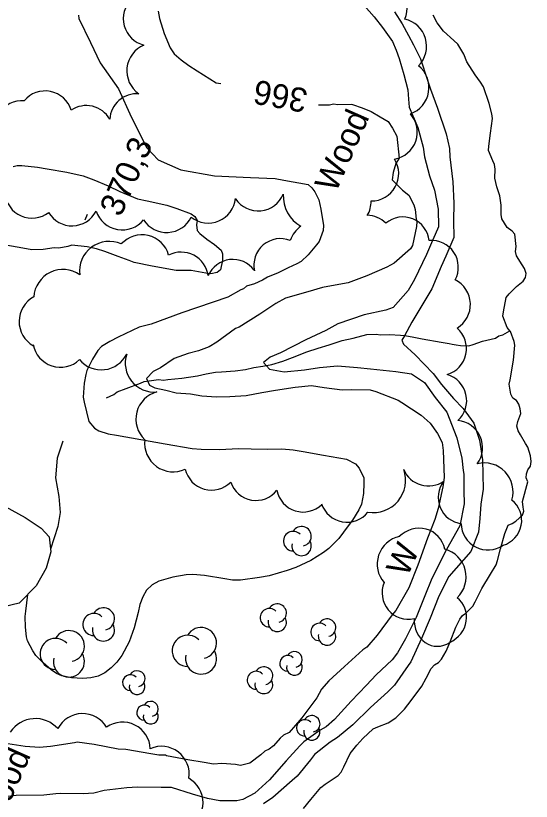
# Model space of a CAD drawing. Extents: x 287698 to 290158, y 5234163 to 5237182.
# Drawn here: x 289223.4 to 289287.7, y 5234946.9 to 5235044.9 of the extents above; entities that cross this region are included whole.
import ezdxf

# ---------------------------------------------------------------- set-up
doc = ezdxf.new("R2010")
doc.units = 0
for name, color, linetype in [('Niveau 1', 7, 'Continuous'), ('Niveau 19', 7, 'Continuous'), ('Niveau 2', 7, 'Continuous'), ('Niveau 21', 7, 'Continuous'), ('Niveau 3', 7, 'Continuous'), ('Niveau 4', 7, 'Continuous'), ('Niveau 44', 7, 'Continuous')]:
    doc.layers.add(name, color=color, linetype=linetype)

msp = doc.modelspace()

# ---------------------------------------------------------------- linework, layer by layer
at = {"layer": 'Niveau 1'}
for points in [[(289223.06, 5235026.08), (289223.56, 5235026.2), (289224.13, 5235026.2), (289226.09, 5235026.02), (289227.29, 5235025.81), (289229.76, 5235025.37), (289231.77, 5235024.91), (289233.12, 5235024.41), (289234.92, 5235023.67), (289236.38, 5235022.96), (289238.57, 5235022.03), (289239.79, 5235021.79), (289242.23, 5235021.24), (289243.46, 5235020.84), (289245.25, 5235020.18), (289245.74, 5235019.83), (289246, 5235019.36), (289245.92, 5235018.8), (289246, 5235018.1), (289246.34, 5235017.73), (289247.21, 5235017.01), (289248.19, 5235016.35), (289249, 5235015.64), (289249.2, 5235015.18), (289249.17, 5235014.41), (289248.93, 5235013.18), (289248.52, 5235012.84), (289247.72, 5235012.68), (289247.11, 5235012.77), (289245.26, 5235013.09), (289243.41, 5235013.11)], [(289243.41, 5235013.11), (289240.42, 5235013.64), (289238.15, 5235014.1), (289237.54, 5235014.37), (289236.14, 5235014.84), (289234.49, 5235015.5), (289233.45, 5235015.82), (289232.28, 5235016.05), (289230.38, 5235016.26), (289229.87, 5235016.09), (289228.77, 5235015.88), (289228.17, 5235015.92), (289226.78, 5235015.74), (289225.37, 5235015.69), (289224.24, 5235015.88), (289221.41, 5235016.38)]]:
    msp.add_lwpolyline(points, dxfattribs=at)
at = {"layer": 'Niveau 19'}
msp.add_lwpolyline([(289229.27, 5234991.84), (289228.56, 5234989.69), (289228.33, 5234987.25), (289228.74, 5234984.92), (289228.92, 5234982.94), (289228.61, 5234981.19), (289227.72, 5234978.34)], dxfattribs=at)
at = {"layer": 'Niveau 2'}
for points in [[(289266.86, 5235046.16), (289268.09, 5235044.77), (289269.16, 5235043.42), (289270.39, 5235041.66), (289270.87, 5235040.58), (289271.22, 5235039.56), (289271.82, 5235037.55), (289272.3, 5235035.66), (289272.4, 5235034.5), (289272.46, 5235033.5), (289272.94, 5235032.4), (289272.94, 5235032.4)], [(289231.21, 5235044.94), (289231.23, 5235044.56), (289232.69, 5235041.53), (289233.92, 5235039.01), (289236.2, 5235035.78), (289237.84, 5235032.21), (289239.74, 5235028.41), (289241.17, 5235026.91), (289243.96, 5235025.68), (289248.2, 5235024.91), (289252.66, 5235024.73)], [(289241.13, 5235045.44), (289241.33, 5235044.55), (289241.9, 5235042.68), (289242.66, 5235040.9), (289243.14, 5235040.15), (289244.01, 5235039.37), (289244.97, 5235038.67), (289246.01, 5235038), (289248.39, 5235036.52), (289248.97, 5235036.42)], [(289270.63, 5235045.39), (289271.59, 5235043.88), (289272.38, 5235042.44), (289273, 5235041.26), (289273.88, 5235039.5), (289274.77, 5235036.87), (289275.14, 5235035.74), (289276.01, 5235033.35), (289277.08, 5235030.14), (289277.52, 5235028.33), (289277.56, 5235027.29), (289277.91, 5235024.15), (289278.07, 5235021.51), (289277.99, 5235019.29), (289278.05, 5235017.24), (289277.06, 5235014.88), (289276.49, 5235013.6), (289275.3, 5235010.82), (289272.81, 5235006.65), (289271.91, 5235004.94), (289271.58, 5235004.43), (289271.76, 5235003.92), (289273.23, 5235002.59), (289275.49, 5235000.25), (289276.53, 5234998.91), (289278.01, 5234997.16), (289279.22, 5234995.91), (289280.54, 5234994.07), (289281.26, 5234991.95), (289281.65, 5234989.5), (289281.72, 5234985.85), (289281.41, 5234983.97), (289281.29, 5234982.17), (289281.11, 5234980.46), (289280.17, 5234978.05), (289277.41, 5234974.95)], [(289261.15, 5235033.79), (289261.49, 5235033.79), (289262.53, 5235033.79), (289263.05, 5235033.9), (289263.57, 5235033.83), (289265.23, 5235033.85)], [(289265.23, 5235033.85), (289265.4, 5235033.82), (289266.6, 5235033.42), (289267.72, 5235032.93), (289268.84, 5235032.27), (289269.87, 5235031.7), (289270.4, 5235030.86), (289270.93, 5235029.85), (289271.23, 5235027.14), (289270.82, 5235026.45), (289270.5, 5235025.34), (289270.35, 5235024.4), (289271.65, 5235023.15), (289272.43, 5235022.49), (289273.04, 5235021.31), (289273.22, 5235020.72), (289273.34, 5235019.53), (289273.42, 5235019.23), (289273.4, 5235018.58), (289272.88, 5235016.23), (289272.63, 5235015.81), (289270.62, 5235014.01), (289269.68, 5235013.53), (289267.19, 5235012.44), (289264.87, 5235011.58), (289264.14, 5235011.43), (289261.66, 5235010.97), (289259.84, 5235010.44), (289257.04, 5235009.65), (289255.84, 5235009.01), (289253.83, 5235007.66), (289251.24, 5235006.04), (289250.8, 5235005.87), (289248.47, 5235004.18), (289247.52, 5235003.6), (289246.17, 5235003.07), (289244.91, 5235002.76), (289243.14, 5235002.12), (289241.45, 5235000.96), (289240.53, 5235000.51), (289239.7, 5234999.65)], [(289272.94, 5235032.4), (289272.99, 5235032.33), (289273.55, 5235030.95), (289274.22, 5235028.51), (289274.38, 5235027.29), (289275.01, 5235024.92), (289275.65, 5235023.14), (289276.11, 5235020.78), (289276.15, 5235018.57), (289275.15, 5235016.28), (289274.64, 5235015.11)], [(289252.66, 5235024.73), (289255.74, 5235024.57), (289256.85, 5235024.38), (289259.88, 5235023.82), (289260.33, 5235023.42), (289260.71, 5235022.91), (289261.19, 5235021.93), (289261.45, 5235020.75), (289261.78, 5235018.72), (289261.73, 5235018.08), (289261.25, 5235016.74), (289260.93, 5235016.33), (289259.88, 5235015.07), (289258.98, 5235014.24), (289258.44, 5235013.94), (289257.36, 5235013.46), (289256.11, 5235012.81), (289254.79, 5235012.27), (289254.18, 5235011.89), (289253.19, 5235011.46), (289252.18, 5235011.17), (289251.79, 5235010.81), (289251.48, 5235010.7)], [(289274.64, 5235015.11), (289273.14, 5235012), (289272.34, 5235010.6), (289270.5, 5235008.5), (289269.58, 5235008.17), (289266.85, 5235007.58), (289263.56, 5235006.47), (289262.07, 5235005.63), (289259.57, 5235004.46), (289256.42, 5235002.85), (289255.12, 5235002.32), (289254.28, 5235001.62), (289255.06, 5235000.79), (289256.86, 5235000.48), (289259.4, 5235000.7), (289261.27, 5235001), (289263.55, 5235001.21), (289266.03, 5235001), (289267.64, 5235000.86), (289270.8, 5235000.5), (289272.77, 5235000.2), (289274.4, 5234999.13), (289275.71, 5234997.28), (289277.19, 5234995.44), (289278.44, 5234992.23), (289279.04, 5234989.71), (289279.23, 5234988.15), (289279.28, 5234987.7), (289279.32, 5234985.62), (289279.35, 5234984), (289278.79, 5234981.27), (289277.15, 5234978.31), (289275.31, 5234974.67), (289274.44, 5234972.52)], [(289251.48, 5235010.7), (289249.84, 5235009.77), (289244.09, 5235007.83), (289240.27, 5235006.4), (289238.76, 5235006.06), (289236.17, 5235004.79), (289235.11, 5235004.27), (289234.08, 5235003.64), (289233.63, 5235003.15), (289232.96, 5235002.03), (289232.25, 5235000.65), (289232.12, 5235000.14), (289231.93, 5234999.04), (289231.79, 5234997.32), (289231.9, 5234996.69), (289232.51, 5234994.27), (289233.2, 5234993.44), (289233.74, 5234993.1), (289234.9, 5234992.75), (289235.97, 5234992.56), (289239, 5234992.03), (289242.01, 5234991.5), (289245.4, 5234990.9), (289246.5, 5234990.81), (289248.83, 5234990.78), (289251.13, 5234990.9), (289252.77, 5234990.88), (289254.79, 5234990.81), (289256.57, 5234990.88), (289258.02, 5234990.74), (289259.23, 5234990.53), (289261.79, 5234990.08), (289264.66, 5234989.57), (289265.76, 5234989.01), (289266.23, 5234988.46), (289266.81, 5234987.24), (289266.83, 5234986.57), (289266.77, 5234985.28), (289266.52, 5234983.97), (289266.19, 5234983.27), (289265.39, 5234981.95), (289264.86, 5234981.27), (289263.69, 5234979.69), (289262.47, 5234978.42), (289261.77, 5234977.92), (289260.22, 5234976.95), (289258.32, 5234976.05), (289257.24, 5234975.67), (289254.99, 5234975.03), (289253.79, 5234974.8), (289251.44, 5234974.48), (289250.44, 5234974.47), (289249.46, 5234974.63), (289246.95, 5234975.07), (289245.47, 5234975.19), (289244.65, 5234975.15), (289243, 5234974.87), (289241.22, 5234974.35), (289240.39, 5234973.89), (289239.71, 5234973.24), (289239.22, 5234972.41), (289238.88, 5234971.43), (289238.66, 5234970.44), (289238.14, 5234968.52), (289237.51, 5234966.78), (289236.62, 5234965.07), (289236.01, 5234964.24), (289235.3, 5234963.54), (289234.5, 5234962.93), (289233.67, 5234962.5), (289232.75, 5234962.32), (289231.73, 5234962.22), (289230.33, 5234962.3), (289229.11, 5234962.54), (289228.45, 5234962.86), (289227.8, 5234963.3), (289226.78, 5234964.17), (289225.9, 5234965.07), (289225.5, 5234965.67), (289224.86, 5234966.9), (289224.73, 5234967.41), (289224.6, 5234968.63), (289224.53, 5234969.96), (289224.64, 5234970.61), (289224.89, 5234972.7)], [(289239.7, 5234999.65), (289240.05, 5234998.81), (289240.74, 5234998.48), (289242.11, 5234998.17), (289243.38, 5234997.85), (289245.18, 5234997.72), (289246.62, 5234997.48), (289248.41, 5234997.35), (289250.11, 5234997.38), (289252.15, 5234997.51), (289254.1, 5234997.89), (289255.79, 5234998.17), (289258.25, 5234998.56), (289260.29, 5234998.77), (289261.86, 5234998.52), (289264.11, 5234998.23), (289265.22, 5234998.27), (289267.63, 5234998.21), (289268.31, 5234998.01), (289271.11, 5234996.95), (289271.57, 5234996.65), (289273.99, 5234995.07), (289275.11, 5234994.08), (289276.03, 5234992.79), (289276.61, 5234991.64), (289276.72, 5234990.66), (289276.83, 5234987.28), (289276.68, 5234986.12), (289276.1, 5234983.44), (289275.69, 5234982.04), (289274.75, 5234979.74), (289273.55, 5234976.35)], [(289273.55, 5234976.35), (289272.43, 5234973.51), (289270.81, 5234970.71), (289270.37, 5234970.15), (289268.5, 5234967.62), (289267.2, 5234966.14), (289266.7, 5234965.8), (289264.4, 5234963.71), (289262.45, 5234961.93), (289261.55, 5234960.88), (289260.95, 5234959.8), (289259.1, 5234957.31), (289259.1, 5234957.31)], [(289277.41, 5234974.95), (289276.18, 5234972.49), (289275.1, 5234969.76), (289274.02, 5234967.22), (289272.67, 5234964.3), (289272.37, 5234963.84), (289270.66, 5234961.39), (289269.8, 5234960.57), (289267.67, 5234958.59), (289265.44, 5234956.43), (289263.55, 5234954.86), (289262.6, 5234954.27), (289260.66, 5234952.73), (289260.18, 5234952.06), (289258.49, 5234950.02), (289257.89, 5234949.5), (289255.47, 5234947.36), (289254.31, 5234946.59)], [(289274.44, 5234972.52), (289273.34, 5234969.82), (289272.04, 5234967.15), (289271.03, 5234965.43), (289270.35, 5234964.54), (289268.35, 5234962.69), (289267.15, 5234961.4), (289265.23, 5234959.38), (289263.15, 5234957.1), (289262.13, 5234956.2), (289261.35, 5234955.79), (289259.32, 5234954.33), (289258.84, 5234953.82), (289257.14, 5234951.93), (289255.03, 5234949.59), (289253.23, 5234947.91), (289251.72, 5234947.13), (289250.98, 5234946.95), (289248.85, 5234946.95), (289247.32, 5234947.26), (289245.42, 5234947.78), (289242.82, 5234948.6), (289241.54, 5234948.6), (289238.59, 5234948.68), (289237.23, 5234948.59), (289234.41, 5234948.23), (289233.11, 5234947.92), (289231.81, 5234947.84), (289228.98, 5234947.89), (289228.38, 5234947.81), (289226.9, 5234947.66)], [(289259.1, 5234957.31), (289257.49, 5234955.47), (289256.8, 5234955.15), (289256.38, 5234954.79), (289255.54, 5234953.83), (289255, 5234953.41), (289254.48, 5234953.14), (289253.95, 5234952.68), (289252.58, 5234951.67), (289251.41, 5234951.38), (289250.82, 5234951.49), (289249.1, 5234951.63), (289248.05, 5234951.55), (289246.88, 5234951.72), (289244.85, 5234952.07), (289242.19, 5234952.58), (289242.05, 5234952.66)], [(289242.05, 5234952.66), (289241.25, 5234952.65), (289240.23, 5234952.82), (289237.13, 5234953.34), (289236.16, 5234953.42), (289233.17, 5234953.98), (289231.05, 5234954.29), (289230.7, 5234954.2), (289227.72, 5234953.72), (289226.36, 5234953.63), (289224.56, 5234953.73), (289222.4, 5234954.06), (289221.09, 5234954.13), (289220.52, 5234953.97), (289217.88, 5234952.85), (289217.39, 5234952.81), (289214.35, 5234952.58), (289213.71, 5234952.64), (289212.19, 5234953.25), (289211.53, 5234953.57)], [(289226.9, 5234947.66), (289223.42, 5234947.61), (289222.04, 5234947.45), (289219.72, 5234947.33), (289218.32, 5234947.45), (289217.12, 5234947.66), (289214.59, 5234947.93), (289213.92, 5234947.72), (289213.39, 5234947.37), (289212.81, 5234946.84)]]:
    msp.add_lwpolyline(points, dxfattribs=at)
at = {"layer": 'Niveau 21'}
msp.add_lwpolyline([(289222.04, 5234983.69), (289224.54, 5234982.31), (289226.54, 5234980.97), (289227.56, 5234979.87), (289227.75, 5234978.03), (289227.18, 5234976), (289225.94, 5234973.76), (289223.81, 5234971.62), (289221.9, 5234971.14)], dxfattribs=at)
at = {"layer": 'Niveau 3'}
msp.add_line((289232.02, 5235019.42), (289232.34, 5235020.15), dxfattribs=at)
at = {"layer": 'Niveau 4'}
for points in [[(289285.05, 5235005.57), (289284.7, 5235006.01), (289284.15, 5235007.4), (289284.23, 5235007.96), (289284.6, 5235009.74), (289284.97, 5235010.2), (289285.86, 5235011.1), (289286.69, 5235011.77), (289287.01, 5235012.22), (289287.1, 5235012.75), (289286.87, 5235013.38), (289286.56, 5235013.82), (289285.89, 5235014.95), (289285.76, 5235015.49), (289285.85, 5235016.12), (289285.67, 5235017.63), (289285.33, 5235018), (289284.72, 5235018.49), (289284.04, 5235019.55), (289283.95, 5235020.09), (289283.94, 5235021.27), (289283.79, 5235022.41), (289283.4, 5235023.54), (289283.18, 5235024.61), (289283.22, 5235025.76), (289283.12, 5235026.33), (289282.94, 5235026.81), (289282.39, 5235028.08), (289282.43, 5235028.6), (289282.61, 5235030.24), (289282.87, 5235032.06), (289282.8, 5235032.66), (289282.46, 5235033.96), (289281.75, 5235036.03), (289281.4, 5235036.6), (289280.71, 5235037.52), (289279.67, 5235039.12), (289279.31, 5235040.08), (289278.54, 5235041.35), (289278.06, 5235041.82), (289276.78, 5235042.98), (289275.96, 5235044), (289275.46, 5235044.94)], [(289234.7, 5234997.21), (289235.61, 5234997.66), (289236.05, 5234997.97), (289237.15, 5234998.41), (289238.93, 5234999.07), (289239.41, 5234999.25), (289240.02, 5234999.36), (289241.18, 5234999.5), (289241.82, 5234999.45), (289242.35, 5234999.5), (289244.12, 5234999.7), (289246.07, 5234999.96), (289247.16, 5235000.24), (289248.31, 5235000.44), (289249.05, 5235000.49), (289250.75, 5235000.58), (289252.04, 5235000.78), (289253.1, 5235001.02), (289254.2, 5235001.17), (289255.32, 5235001.4), (289256.73, 5235001.8), (289257.93, 5235002.24), (289259.7, 5235002.96), (289261.12, 5235003.44), (289262.49, 5235003.83), (289264.11, 5235004.36), (289265.5, 5235004.66), (289267.21, 5235005.11), (289268.37, 5235005.15), (289268.89, 5235005.08), (289270.01, 5235005.12), (289271.38, 5235005.06), (289271.94, 5235004.99), (289273.06, 5235004.79), (289274.1, 5235004.6), (289276.47, 5235004.19), (289277.45, 5235004.01), (289277.85, 5235003.94), (289278.36, 5235003.85), (289278.87, 5235003.76), (289279.92, 5235003.72), (289280.47, 5235003.87), (289281.63, 5235004.31), (289282.16, 5235004.44), (289283.25, 5235004.66), (289283.67, 5235004.95), (289284.16, 5235005.08), (289285.05, 5235005.57), (289285.05, 5235005.57)], [(289286.61, 5234984.29), (289287.27, 5234986.75), (289287.07, 5234987.23), (289287.12, 5234987.73), (289287.27, 5234988.23), (289287.62, 5234988.72), (289287.72, 5234989.27), (289287.6, 5234989.98), (289287.3, 5234991.07), (289286.99, 5234991.51), (289286.38, 5234992.61), (289286.08, 5234993.11), (289285.92, 5234993.69), (289286.02, 5234994.26), (289286.4, 5234995.29), (289286.34, 5234995.87), (289286.16, 5234996.45), (289285.87, 5234996.88), (289285.42, 5234997.19), (289285.18, 5234997.7), (289284.97, 5234998.93), (289285.07, 5234999.46), (289285.5, 5235001.92), (289285.68, 5235003.78), (289285.57, 5235004.27), (289285.11, 5235005.49), (289285.05, 5235005.57)], [(289277.59, 5234966.8), (289278.32, 5234968.64), (289278.8, 5234969.63), (289279.14, 5234970.06), (289279.54, 5234970.37), (289280.44, 5234971.23), (289280.72, 5234971.77), (289281.54, 5234973.45), (289282.61, 5234975.25), (289283.34, 5234976.39), (289283.52, 5234976.94), (289283.88, 5234978.4), (289284.41, 5234980.3), (289284.82, 5234981.36), (289285.32, 5234981.54), (289285.79, 5234981.86), (289286.62, 5234982.57), (289286.77, 5234983.09), (289286.7, 5234983.59), (289286.61, 5234984.29)], [(289259.29, 5234945.98), (289260.19, 5234947.14), (289261.46, 5234948.62), (289262, 5234949.02), (289263.62, 5234950.11), (289264, 5234950.55), (289264.34, 5234951.2), (289265.12, 5234952.87), (289265.93, 5234953.91), (289266.7, 5234954.73), (289267.97, 5234955.92), (289268.55, 5234956.19), (289269.85, 5234956.69), (289270.81, 5234957.29), (289271.9, 5234958.4), (289272.74, 5234959.47), (289274.05, 5234961.27), (289274.59, 5234962.27), (289275.21, 5234963.48), (289275.65, 5234963.91), (289276.12, 5234964.23), (289276.51, 5234964.61), (289277.09, 5234965.63), (289277.59, 5234966.8)]]:
    msp.add_lwpolyline(points, dxfattribs=at)
at = {"layer": 'Niveau 44'}
for centre, radius, start, end in [((289236.666, 5235021.615), 3.439, 198.74081, 320.76876), ((289276.293, 5234996.886), 3.364, 312.11974, 74.0155), ((289278.255, 5234991.011), 3.392, 323.43708, 85.01841), ((289259.049, 5234979.961), 1.218, 282.26917, 149.72626), ((289258.002, 5234979.352), 1.218, 44.11537, 269.80396), ((289259.049, 5234978.744), 1.218, 166.93686, 29.62123), ((289256.01, 5234970.374), 1.147, 282.26917, 149.72626), ((289233.127, 5234968.957), 1.384, 44.11537, 269.80396), ((289234.318, 5234969.649), 1.384, 282.26917, 149.72626), ((289255.024, 5234969.8), 1.147, 44.11537, 269.80396), ((289256.01, 5234969.227), 1.147, 166.93686, 29.62123), ((289262.229, 5234968.566), 1.094, 282.26917, 149.72626), ((289234.318, 5234968.265), 1.384, 166.93686, 29.62123), ((289246.505, 5234966.64), 1.938, 282.26917, 149.72626), ((289261.288, 5234968.019), 1.094, 44.11537, 269.80396), ((289230.013, 5234966.259), 1.935, 282.26917, 149.72626), ((289244.838, 5234965.671), 1.938, 44.11537, 269.80396), ((289262.229, 5234967.472), 1.094, 166.93686, 29.62123), ((289228.349, 5234965.291), 1.935, 44.11537, 269.80396), ((289230.013, 5234964.324), 1.935, 166.93686, 29.62123), ((289246.505, 5234964.702), 1.938, 166.93686, 29.62123), ((289258.153, 5234964.598), 0.984, 282.26917, 149.72626), ((289257.307, 5234964.106), 0.984, 44.11537, 269.80396), ((289254.337, 5234962.557), 1.114, 282.26917, 149.72626), ((289258.153, 5234963.614), 0.984, 166.93686, 29.62123), ((289237.676, 5234961.706), 0.987, 44.11537, 269.80396), ((289238.525, 5234962.2), 0.987, 282.26917, 149.72626), ((289253.379, 5234962), 1.114, 44.11537, 269.80396), ((289238.525, 5234961.213), 0.987, 166.93686, 29.62123), ((289254.337, 5234961.442), 1.114, 166.93686, 29.62123), ((289239.417, 5234957.955), 0.941, 44.11537, 269.80396), ((289240.226, 5234958.425), 0.941, 282.26917, 149.72626), ((289240.226, 5234957.485), 0.941, 166.93686, 29.62123), ((289260.329, 5234956.567), 1.021, 282.26917, 149.72626), ((289259.451, 5234956.057), 1.021, 44.11537, 269.80396), ((289260.329, 5234955.547), 1.021, 166.93686, 29.62123)]:
    msp.add_arc(centre, radius, start, end, dxfattribs=at)
for centre, major_axis, ratio, start_param, end_param in [((289268.786, 5235045.868), (-1.543, 3.084), 0.994093, 3.833101, 5.988588), ((289240.193, 5235044.533), (-3.363, -0.519), 0.999678, 5.331315, 7.459672), ((289271.168, 5235041.081), (3.331, 0.994), 0.999219, 5.218184, 7.343204), ((289240.728, 5235038.013), (1.437, -3.179), 0.999995, 3.113783, 5.245327), ((289271.466, 5235035.94), (3.388, -0.808), 0.999151, 5.287086, 7.409991), ((289227.045, 5235032.11), (-3.334, 0.653), 0.999937, 3.635979, 5.788799), ((289238.495, 5235031.777), (-1.793, -2.878), 0.999984, 3.632376, 5.206684), ((289224.156, 5235030.882), (-1.833, -2.858), 0.999984, 3.634174, 5.790604), ((289232.169, 5235030.285), (-2.995, 1.605), 0.999859, 4.159019, 5.790036), ((289270.047, 5235030.393), (3.236, -1.2), 0.994842, 5.244516, 7.360748), ((289267.701, 5235025.232), (3.012, -1.73), 0.991864, 5.235527, 7.348842), ((289225.41, 5235023.032), (3.127, -1.321), 0.99986, 3.633576, 5.7693), ((289253.634, 5235023.938), (3.378, 0.333), 0.999938, 3.632408, 5.79237), ((289261.046, 5235022.376), (-2.318, -3.604), 0.999568, 5.222115, 6.349873), ((289247.414, 5235022.408), (2.445, -2.343), 0.999674, 4.794274, 6.955218), ((289264.581, 5235021.678), (1.698, -2.666), 0.991386, 0.443012, 1.039814), ((289230.396, 5235022.077), (3.397, 0.051), 0.999937, 3.663185, 5.788709), ((289242.211, 5235021.264), (-0.605, -3.355), 0.999927, 5.45515, 7.582221), ((289267.176, 5235016.613), (-0.133, 3.378), 0.999925, 5.461027, 6.221886), ((289271.68, 5235016.466), (2.179, 2.516), 0.994889, 5.536616, 7.692729), ((289260.814, 5235015.856), (-3.273, -0.613), 0.999206, 5.113753, 5.79155), ((289239.121, 5235014.085), (0.999, 3.329), 0.999008, 5.281917, 7.408578), ((289256.421, 5235013.765), (-2.535, -2.155), 0.999416, 3.632929, 5.791849), ((289235.032, 5235013.053), (-2.2, 2.968), 0.999611, 5.221636, 7.347648), ((289275.283, 5235013.522), (-1.84, 2.777), 0.999853, 3.635775, 5.789003), ((289243.994, 5235011.941), (-2.825, 1.997), 0.998152, 3.911532, 5.786513), ((289250.475, 5235011.16), (-3.294, -0.501), 0.999414, 3.634941, 5.73083), ((289229.268, 5235009.593), (-1.305, 3.404), 0.999453, 5.301768, 7.428492), ((289276.677, 5235008.871), (3.442, 0.155), 0.999334, 5.214479, 7.344825), ((289227.255, 5235006.751), (-3.177, 1.387), 0.998471, 5.6115, 7.759248), ((289276.222, 5235003.374), (3.328, -0.713), 0.999994, 5.220868, 7.343457), ((289228.95, 5235004.478), (3.403, -0.541), 0.998103, 3.470673, 5.63222), ((289234.049, 5235004.262), (0.663, -3.482), 0.999666, 5.220114, 7.206892), ((289240.637, 5235001.549), (-2.959, -2.047), 0.999995, 5.355832, 7.34985), ((289241.893, 5234994.564), (-3.413, 0.863), 0.999995, 5.216404, 7.34665), ((289243.028, 5234991.573), (-2.096, -2.895), 0.999954, 5.219273, 7.343393), ((289281.877, 5234985.533), (-3.435, 0.977), 0.999995, 3.119405, 5.24355), ((289247.814, 5234989.092), (-0.922, -3.243), 0.999994, 5.217619, 7.346378), ((289268.024, 5234986.931), (3.116, -2.531), 0.999203, 5.220434, 7.311234), ((289274.882, 5234989.558), (3.298, -0.481), 0.999202, 3.677142, 5.473622), ((289253.36, 5234987.752), (3.278, -0.573), 0.999416, 3.633303, 5.791475), ((289279.435, 5234984.811), (-3.221, -0.864), 0.992818, 5.361823, 7.454081), ((289259.249, 5234986.304), (3.169, -1.006), 0.999595, 3.631985, 5.792793), ((289264.716, 5234985.044), (3.279, -0.584), 0.999416, 3.633765, 5.791013), ((289283.194, 5234981.951), (3.308, -0.398), 0.980191, 5.133458, 7.290542), ((289273.631, 5234977.578), (1.946, 2.812), 0.974035, 5.535422, 7.688654), ((289282.309, 5234981.588), (2.966, -1.534), 0.999593, 3.636669, 5.788109), ((289271.773, 5234976.561), (-1.079, -3.247), 0.957367, 3.635036, 5.789742), ((289275.897, 5234974.86), (3.572, 0.937), 0.979742, 5.229091, 7.321337), ((289272.473, 5234973.001), (-2.267, -2.57), 0.97202, 5.062132, 7.210452), ((289276.315, 5234969.635), (2.792, 1.988), 0.920728, 4.511226, 6.576154), ((289276.118, 5234969.636), (-0.601, -3.363), 0.877196, 4.849775, 6.977734), ((289231.715, 5234954.346), (-0.098, 3.494), 0.999807, 5.220172, 7.342795), ((289225.824, 5234953.457), (-0.843, 3.663), 0.999982, 5.218407, 7.04117), ((289236.72, 5234953.317), (-3.441, 0.29), 0.999341, 3.267159, 5.414293), ((289241.567, 5234950.308), (-3.251, -1.168), 0.99816, 2.637671, 4.784395), ((289243.311, 5234946.753), (3.253, -1.131), 0.998728, 5.529193, 7.68382)]:
    msp.add_ellipse(centre, major_axis=major_axis, ratio=ratio, start_param=start_param, end_param=end_param, dxfattribs=at)

# ---------------------------------------------------------------- texts
at = {"layer": 'Niveau 2'}
msp.add_text('366', height=2.9999, rotation=169.62245, dxfattribs=at).set_placement((289259.97, 5235035.71))
at = {"layer": 'Niveau 3'}
msp.add_text('370,3', height=3, rotation=66.1217, dxfattribs=at).set_placement((289236.47, 5235019.68))
at = {"layer": 'Niveau 44'}
for s, p in [('Wood', (289263.32, 5235022.71)), ('W', (289272.25, 5234974.77)), ('Wood', (289221.07, 5234943.11))]:
    msp.add_text(s, height=3, rotation=66.1217, dxfattribs=at).set_placement(p)

doc.saveas('drawing.dxf')
